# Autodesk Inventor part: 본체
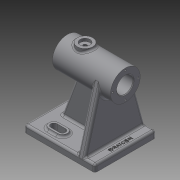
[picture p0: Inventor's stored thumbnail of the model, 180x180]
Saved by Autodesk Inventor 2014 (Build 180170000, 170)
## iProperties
Created: 2019-10
Part Number: 본체
Material: Generic
Document SubType Name: Modeling
Designer: kh
Density: 1 g/cm^3
Appearance: Default
Author: kh
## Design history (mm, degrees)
sketch "Sketch1"
  geometry: L1 (-50, -43)-(50, -43); L2 (50, -43)-(50, 43); L3 (50, 43)-(-50, 43); L4 (-50, 43)-(-50, -43); L5 (-50, -43)-(50, 43); L6 (50, -43)-(-50, 43); 1 further point
  constraints: 12 end point, 2 midpoint, 2 parallel, 1 horizontal, 1 perpendicular
  dimensions: "d0" = 100 distance of L2.end L3.end; "d1" = 86 distance of L1.end L2.end
extrude "Extrusion1" new body sketch "Sketch1" distance "d2" = 10; taper "d3" = 0 deg
sketch "Sketch2"
  geometry: L1 (50, 0)-(-50, 0) reference; L2 (50, 107)-(50, 86); L3 (50, 86)-(-32, 86); L4 (-32, 86)-(-32, 107); L5 (-32, 107)-(50, 107); 2 further points
  constraints: 8 end point, 2 parallel, 2 perpendicular, 1 midpoint, 1 vertical alignment
  dimensions: "d9" = 42 diameter of L5 L3; "d10" = 86 distance from line of L2.end L1; "d11" = 82 distance between parallel lines of L4 L2
revolve "Revolution2" sketch "Sketch2" stored, may be unused: angle "d12" = 90 deg
sketch "Sketch3"
  geometry: L1 (50, 65)-(50, 107) reference; L2 (-32, 65)-(-32, 107) reference; L3 (-32, 86)-(50, 86); L4 (-32, 86)-(30, 86); L5 (30, 86)-(30, 100.5); L6 (30, 100.5)-(-32, 100.5); L7 (-32, 100.5)-(-32, 86); L8 (30, 86)-(50, 86); L9 (50, 86)-(50, 97.5); L10 (50, 97.5)-(30, 97.5); L11 (30, 97.5)-(30, 86); 1 further point
  constraints: 18 end point, 4 parallel, 2 horizontal, 2 midpoint, 2 perpendicular, 1 point on line
  dimensions: "d13" = 29 diameter of L6 L3; "d14" = 23 diameter of L10 L3; "d15" = 62 distance between parallel lines of L5 L2
revolve "Revolution3" sketch "Sketch3" stored, may be unused: angle "d16" = 90 deg
workplane "Work Plane1"
fillet "Fillet1" dims "d35" = 3
fillet "Fillet2" dims "d36" = 3
workplane "Work Plane3"
sketch "Sketch16"
  geometry: L1 (5.48, 20.272)-(-78.217, 42.896); L2 (5.48, -20.272)-(-78.217, -42.896); L3 (-76, 40)-(-76, -40); A1 r 3 centre (-79, -40) between (-79, -43) and (-76, -40) reference; A2 r 21 centre (0, 0) between (5.48, 20.272) and (5.48, -20.272) reference; A3 r 21 centre (0, 0) between (5.48, 20.272) and (5.48, -20.272); A4 r 3 centre (-79, 40) between (-76, 40) and (-79, 43) reference; A5 r 3 centre (-79, 40) between (-76, 40) and (-78.217, 42.896); A6 r 3 centre (-79, -40) between (-78.217, -42.896) and (-76, -40); 1 further point
  constraints: 10 point on circle, 7 tangent, 6 end point, 3 centre point, 2 concentric, 1 vertical
sketch "Sketch17"
  geometry: L1 (50, -40)-(50, 40) reference; L2 (32, 21)-(32, -21) reference; C1 r 11 at (7, 0); 2 further points
  constraints: 1 centre point, 1 horizontal alignment, 1 midpoint
  dimensions: "d41" = 22 diameter of C1; "d43" = 25 distance from line of C1.centre L2
extrude "Extrusion4" join sketch "Sketch17" stored distance "d44" = 10; taper "d45" = 0 deg
hole "Hole2" diameter "d48" = 4.917; stored, may be unused: countersink angle "d52" = 90 deg, drill point angle "d54" = 118 deg; dims "d46" = 10, "d47" = 10, "d49" = 6, "d50" = 14, "d51" = 4, "d53" = 8
sketch "Sketch21"
  geometry: L1 (-47, 10)-(47, 10) reference; L2 (-32, 65)-(50, 65) reference; L3 (-35, 10)-(-14.982, 65); A1 r 3 centre (-47, 7) between (-47, 10) and (-50, 7) reference; 1 further point
  constraints: 2 end point, 2 point on line
  dimensions: "d62" = 70 deg angle of L1 L3; "d63" = 15 horizontal distance of A1.end L3.start
sketch "Sketch22"
  geometry: C1 r 11.5 at (0, 0) reference; A1 r 18 centre (0, 0) between (18, 0) and (0, 18); 3 further points
  constraints: 4 point on circle, 1 centre point, 1 coincident
  dimensions: "d70" = 36 diameter of A1
hole "Hole3" sketch "Sketch22" at (18, 0), (0, 18), (-18, 0), (0, -18) diameter "d71" = 2.459; stored, may be unused: countersink angle "d75" = 90 deg, drill point angle "d77" = 118 deg; dims "d72" = 8, "d73" = 14, "d74" = 4, "d76" = 10
sketch "Sketch23"
  geometry: C1 r 14.5 at (0, 0) reference; A1 r 18 centre (0, 0) between (-18, 0) and (0, -18); 3 further points
  constraints: 4 point on circle, 1 centre point, 1 coincident
  dimensions: "d78" = 36 diameter of A1
hole "Hole4" sketch "Sketch23" at (-18, 0), (0, -18), (18, 0), (0, 18) diameter "d79" = 2.459; stored, may be unused: countersink angle "d83" = 90 deg, drill point angle "d85" = 118 deg; dims "d80" = 8, "d81" = 14, "d82" = 4, "d84" = 10
chamfer "Chamfer1" distance "d86" = 1; stored, may be unused: second distance "d87" = 2, angle "d88" = 45 deg
fillet "Fillet3" dims "d89" = 3
extrude "Extrusion5" join sketch "Sketch16" distance "d93" = 10; taper "d94" = 0 deg
feature "Rib2" dims "d95" = 1, "d96" = 10, "d97" = 0, "d98" = 0, "d99" = 1, "d100" = 1
fillet "Fillet7" dims "d101" = 3
fillet "Fillet8" dims "d102" = 3
sketch "Sketch24"
  geometry: L1 (24, -27)-(12, -27); L2 (24, -20)-(12, -20); L3 (12, -34)-(24, -34); L4 (50, -40)-(50, 40) reference; A1 r 7 centre (24, -27) between (24, -34) and (24, -20); A2 r 7 centre (12, -27) between (12, -20) and (12, -34); 2 further points
  constraints: 8 end point, 4 point on circle, 4 tangent, 2 centre point, 1 horizontal, 1 midpoint, 1 parallel
  dimensions: "d103" = 27 vertical distance of point (18, -27) point (0, 0); "d104" = 14 distance between parallel lines of L3 L2; "d118" = 12 distance of L1.start L1.end; "d119" = 26 distance from line of L1.start L4
extrude "Extrusion6" join sketch "Sketch24" distance "d107" = 3; taper "d108" = 0 deg
sketch "Sketch25"
  geometry: L1 (24, -34)-(12, -34) reference; L2 (24, -34)-(12, -34) reference; L3 (12, -20)-(24, -20) reference; L4 (-22, 8)-(-22, 38.378) reference; L5 (30.716, 8)-(-22, 8) reference; L6 (37.101, -2)-(37.101, 2) reference; L7 (-22, -8)-(30.716, -8) reference; L8 (-22, -38.378)-(-22, -8) reference; L9 (47, -40)-(-22.208, -40) reference; L10 (47, 40)-(47, -40) reference; L11 (-22.208, 40)-(47, 40) reference; L12 (24, -27)-(12, -27); L13 (24, -22.5)-(12, -22.5); L14 (12, -31.5)-(24, -31.5); A1 r 7 centre (24, -27) between (24, -34) and (24, -20) reference; A2 r 7 centre (12, -27) between (12, -20) and (12, -34) reference; A3 r 4.5 centre (24, -27) between (24, -31.5) and (24, -22.5); A4 r 4.5 centre (12, -27) between (12, -22.5) and (12, -31.5); 6 further points; 4 other entities
  constraints: 8 end point, 4 point on circle, 4 tangent, 2 centre point, 2 parallel, 1 midpoint, 4 other
  dimensions: "d109" = 9 distance between parallel lines of L14 L13
extrude "Extrusion7" cut sketch "Sketch25" stored distance "d110" = 10; taper "d111" = 0 deg
fillet "Fillet9" dims "d112" = 3
mirror "Mirror1"
workplane "Work Plane4"
sketch "Sketch26"
  geometry: L1 (-40.598, 16.592)-(-40.598, -16.592); L2 (-40.598, -16.592)-(-45.402, -16.592); L3 (-45.402, -16.592)-(-45.402, 16.592); L4 (-45.402, 16.592)-(-40.598, 16.592); L5 (-40.598, 16.592)-(-45.402, -16.592); L6 (-40.598, -16.592)-(-45.402, 16.592); L7 (47, 43)-(-47, 43) reference; L8 (-50, 40)-(-50, -40) reference; 2 further points
  constraints: 4 end point, 1 midpoint, 2 other
  dimensions: "d114" = 43 distance from line of point (-43, 0) L7; "d115" = 7 distance from line of L8 point (-43, 0)
emboss "Emboss1" sketch "Sketch26" dims "d0" = 100, "d1" = 86, "d116" = 0.5, "d117" = 0
fillet "Fillet10" dims "d120" = 3
body "Solid1"
node "Projected Loop1"
node "Projected Loop7"
other parameters: "d38" = -15, "d113" = 6.25
